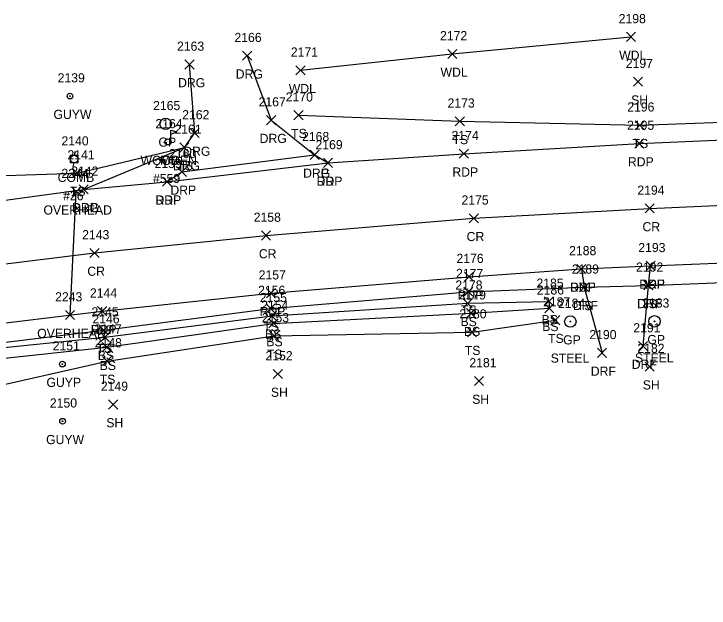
# Model space of a CAD drawing. Extents: x 1611797 to 1633212, y 298978 to 305475.
# Drawn here: x 1614651.7 to 1614804, y 301422 to 301552.1 of the extents above; entities that cross this region are included whole.
import ezdxf

# ---------------------------------------------------------------- set-up
doc = ezdxf.new("R2010")
doc.units = 0
for name, color, linetype in [('L_A', 7, 'Continuous'), ('L_C', 7, 'Continuous'), ('L_I', 7, 'Continuous'), ('L_TIC', 7, 'Continuous'), ('LAWA', 7, 'Continuous'), ('LELB', 7, 'Continuous'), ('LMB', 7, 'Continuous'), ('P_A', 7, 'Continuous'), ('P_I', 7, 'Continuous'), ('P_TIC', 7, 'Continuous'), ('PET', 7, 'Continuous'), ('PRC', 7, 'Continuous'), ('R_A', 7, 'Continuous'), ('R_C', 7, 'Continuous'), ('R_I', 7, 'Continuous'), ('R_TIC', 7, 'Continuous'), ('RDF', 7, 'Continuous'), ('RDG', 7, 'Continuous'), ('RDP', 7, 'Continuous'), ('RGP', 7, 'Continuous'), ('U_A', 7, 'Continuous'), ('U_C', 7, 'Continuous'), ('U_I', 7, 'Continuous'), ('U_TIC', 7, 'Continuous'), ('UCO', 7, 'Continuous'), ('UP', 7, 'Continuous'), ('UPGW', 7, 'Continuous')]:
    doc.layers.add(name, color=color, linetype=linetype)

msp = doc.modelspace()

# ---------------------------------------------------------------- linework, layer by layer
at = {"layer": 'L_TIC'}
for points in [[(1614785.88, 301546.07), (1614787.88, 301548.07)], [(1614787.88, 301546.07), (1614785.88, 301548.07)], [(1614746.75, 301542.34), (1614748.75, 301544.34)], [(1614748.75, 301542.34), (1614746.75, 301544.34)], [(1614713.52, 301538.76), (1614715.52, 301540.76)], [(1614715.52, 301538.76), (1614713.52, 301540.76)], [(1614787.44, 301536.26), (1614789.44, 301538.26)], [(1614789.44, 301536.26), (1614787.44, 301538.26)], [(1614713.06, 301528.93), (1614715.06, 301530.93)], [(1614715.06, 301528.93), (1614713.06, 301530.93)], [(1614748.4, 301527.59), (1614750.4, 301529.59)], [(1614750.4, 301527.59), (1614748.4, 301529.59)], [(1614787.82, 301526.73), (1614789.82, 301528.73)], [(1614789.82, 301526.73), (1614787.82, 301528.73)], [(1614688.07, 301521.87), (1614690.07, 301523.87)], [(1614690.07, 301521.87), (1614688.07, 301523.87)], [(1614664.6, 301516.26), (1614666.6, 301518.26)], [(1614666.6, 301516.26), (1614664.6, 301518.26)], [(1614775.62, 301491.25), (1614777.62, 301493.25)], [(1614777.62, 301491.25), (1614775.62, 301493.25)], [(1614789.7, 301491.68), (1614791.7, 301493.68)], [(1614791.7, 301491.68), (1614789.7, 301493.68)], [(1614750.26, 301490.29), (1614752.26, 301492.29)], [(1614752.26, 301490.29), (1614750.26, 301492.29)], [(1614767.89, 301488.17), (1614769.89, 301490.17)], [(1614769.89, 301488.17), (1614767.89, 301490.17)], [(1614706.96, 301486.6), (1614708.96, 301488.6)], [(1614708.96, 301486.6), (1614706.96, 301488.6)], [(1614750.11, 301487.75), (1614752.11, 301489.75)], [(1614752.11, 301487.75), (1614750.11, 301489.75)], [(1614768.01, 301486.67), (1614770.01, 301488.67)], [(1614770.01, 301486.67), (1614768.01, 301488.67)], [(1614768.01, 301486.67), (1614770.01, 301488.67)], [(1614770.01, 301486.67), (1614768.01, 301488.67)], [(1614707.28, 301485.02), (1614709.28, 301487.02)], [(1614709.28, 301485.02), (1614707.28, 301487.02)], [(1614750.86, 301485.59), (1614752.86, 301487.59)], [(1614752.86, 301485.59), (1614750.86, 301487.59)], [(1614707.59, 301483.35), (1614709.59, 301485.35)], [(1614709.59, 301483.35), (1614707.59, 301485.35)], [(1614769.32, 301484.06), (1614771.32, 301486.06)], [(1614771.32, 301484.06), (1614769.32, 301486.06)], [(1614670.43, 301481.88), (1614672.43, 301483.88)], [(1614672.43, 301481.88), (1614670.43, 301483.88)], [(1614670.68, 301480.35), (1614672.68, 301482.35)], [(1614672.68, 301480.35), (1614670.68, 301482.35)], [(1614707.74, 301480.62), (1614709.74, 301482.62)], [(1614709.74, 301480.62), (1614707.74, 301482.62)], [(1614751.08, 301481.44), (1614753.08, 301483.44)], [(1614753.08, 301481.44), (1614751.08, 301483.44)], [(1614671.08, 301478.14), (1614673.08, 301480.14)], [(1614673.08, 301478.14), (1614671.08, 301480.14)], [(1614671.14, 301475.12), (1614673.14, 301477.12)], [(1614673.14, 301475.12), (1614671.14, 301477.12)], [(1614789.98, 301473.89), (1614791.98, 301475.89)], [(1614791.98, 301473.89), (1614789.98, 301475.89)], [(1614708.54, 301472.28), (1614710.54, 301474.28)], [(1614710.54, 301472.28), (1614708.54, 301474.28)], [(1614752.62, 301470.74), (1614754.62, 301472.74)], [(1614754.62, 301470.74), (1614752.62, 301472.74)], [(1614672.49, 301465.61), (1614674.49, 301467.61)], [(1614674.49, 301465.61), (1614672.49, 301467.61)]]:
    msp.add_lwpolyline(points, dxfattribs=at)
at = {"layer": 'LAWA'}
msp.add_lwpolyline([(1614714.52, 301539.76), (1614747.75, 301543.34), (1614786.88, 301547.07)], dxfattribs=at)
at = {"layer": 'LELB'}
for points in [[(1614714.06, 301529.93), (1614749.4, 301528.59), (1614788.82, 301527.73), (1614827.02, 301529.13), (1614870.26, 301533.86), (1614915.48, 301532.19), (1614947.38, 301533.98), (1615003.28, 301531.36), (1615030.43, 301531.47), (1615038.75, 301539.3), (1615042.32, 301548.18)], [(1614431.54, 301482.84), (1614462.05, 301487.3), (1614494.87, 301495.91), (1614519.67, 301504.14), (1614559.97, 301510.18), (1614596.29, 301511.9), (1614638.57, 301516.35), (1614665.6, 301517.26), (1614689.07, 301522.87)], [(1614397.99, 301442.92), (1614427.41, 301447.99), (1614467.33, 301454.21), (1614500.14, 301459.48), (1614527.47, 301463.02), (1614565.7, 301469.85), (1614602.21, 301474.32), (1614642.74, 301479.39), (1614671.43, 301482.88), (1614707.96, 301487.6), (1614751.26, 301491.29), (1614776.62, 301492.25), (1614790.7, 301492.68), (1614828.78, 301494.15), (1614870.95, 301494.61), (1614916.31, 301494.84), (1614940.92, 301495.39), (1614991.32, 301496.48), (1615024.25, 301496.97), (1615079.65, 301497.8)], [(1614388.68, 301423.66), (1614397.1, 301437.78), (1614427.86, 301446.85), (1614467.6, 301452.72), (1614486.89, 301454.32), (1614500.85, 301457.06), (1614528.06, 301461.07), (1614566.51, 301467.1), (1614602.68, 301472.69), (1614643.17, 301478.4), (1614671.68, 301481.35), (1614708.28, 301486.02), (1614751.11, 301488.75), (1614768.89, 301489.17), (1614769.01, 301487.67)], [(1614397.1, 301437.78), (1614428.41, 301444.54), (1614468.12, 301450.7), (1614487.22, 301452.99), (1614500.88, 301455.16), (1614528.71, 301458.71), (1614567.07, 301464.5), (1614603.04, 301470.65), (1614643.55, 301476.12), (1614672.08, 301479.14), (1614708.59, 301484.35), (1614751.86, 301486.59), (1614769.01, 301487.67)], [(1614398.42, 301422.03), (1614407.58, 301431.9), (1614428.91, 301436.83), (1614470.35, 301441.15), (1614511.39, 301446.9), (1614531.19, 301448.83), (1614567.14, 301456.99), (1614604.55, 301462.93), (1614643.66, 301469.63), (1614672.14, 301476.12), (1614708.74, 301481.62), (1614752.08, 301482.44), (1614770.32, 301485.06)]]:
    msp.add_lwpolyline(points, dxfattribs=at)
at = {"layer": 'LMB'}
for p, q in [((1614686.12, 301526.68), (1614687.41, 301526.3)), ((1614686.12, 301524.09), (1614686.12, 301526.68)), ((1614686.12, 301525.78), (1614687.4, 301526.29)), ((1614685.47, 301524.08), (1614685.47, 301524.08))]:
    msp.add_line(p, q, dxfattribs=at)
msp.add_circle((1614685.47, 301524.08), 0.656, dxfattribs=at)
at = {"layer": 'P_TIC'}
for points in [[(1614787.72, 301522.73), (1614789.72, 301524.73)], [(1614789.72, 301522.73), (1614787.72, 301524.73)], [(1614749.28, 301520.49), (1614751.28, 301522.49)], [(1614751.28, 301520.49), (1614749.28, 301522.49)], [(1614719.54, 301518.49), (1614721.54, 301520.49)], [(1614721.54, 301518.49), (1614719.54, 301520.49)], [(1614684.25, 301514.36), (1614686.25, 301516.36)], [(1614686.25, 301514.36), (1614684.25, 301516.36)], [(1614666, 301512.69), (1614668, 301514.69)], [(1614668, 301512.69), (1614666, 301514.69)], [(1614789.97, 301508.52), (1614791.97, 301510.52)], [(1614791.97, 301508.52), (1614789.97, 301510.52)], [(1614751.46, 301506.37), (1614753.46, 301508.37)], [(1614753.46, 301506.37), (1614751.46, 301508.37)], [(1614705.96, 301502.6), (1614707.96, 301504.6)], [(1614707.96, 301502.6), (1614705.96, 301504.6)], [(1614668.39, 301498.77), (1614670.39, 301500.77)], [(1614670.39, 301498.77), (1614668.39, 301500.77)], [(1614790.19, 301495.95), (1614792.19, 301497.95)], [(1614792.19, 301495.95), (1614790.19, 301497.95)], [(1614775.03, 301495.28), (1614777.03, 301497.28)], [(1614777.03, 301495.28), (1614775.03, 301497.28)], [(1614750.42, 301493.58), (1614752.42, 301495.58)], [(1614752.42, 301493.58), (1614750.42, 301495.58)], [(1614707.04, 301489.97), (1614709.04, 301491.97)], [(1614709.04, 301489.97), (1614707.04, 301491.97)], [(1614670.08, 301486.02), (1614672.08, 301488.02)], [(1614672.08, 301486.02), (1614670.08, 301488.02)]]:
    msp.add_lwpolyline(points, dxfattribs=at)
at = {"layer": 'PET'}
for points in [[(1614353.18, 301466.45), (1614396.11, 301473.72), (1614432.71, 301479.37), (1614462.6, 301484.02), (1614495.94, 301489.18), (1614521.44, 301493.19), (1614561.65, 301499.05), (1614597.5, 301504.18), (1614639.09, 301509.88), (1614667, 301513.69), (1614685.25, 301515.36), (1614720.54, 301519.49), (1614750.28, 301521.49), (1614788.72, 301523.73), (1614827.23, 301525.41)], [(1614357.07, 301439.35), (1614396.41, 301445), (1614427.12, 301450.7), (1614466.81, 301457.75), (1614499.64, 301462.71), (1614526.79, 301467.08), (1614565.37, 301472.77), (1614601.94, 301478.15), (1614641.98, 301483.54), (1614671.08, 301487.02), (1614708.04, 301490.97), (1614751.42, 301494.58), (1614776.03, 301496.28), (1614791.19, 301496.95), (1614828.91, 301498.47)]]:
    msp.add_lwpolyline(points, dxfattribs=at)
at = {"layer": 'PRC'}
msp.add_lwpolyline([(1614363.42, 301453.92), (1614394.65, 301458.77), (1614425.51, 301463.7), (1614464.79, 301470.26), (1614497.93, 301475.41), (1614523.39, 301479.49), (1614563.69, 301485.47), (1614599.72, 301490.73), (1614640.43, 301496.25), (1614669.39, 301499.77), (1614706.96, 301503.6), (1614752.46, 301507.37), (1614790.97, 301509.52), (1614828.29, 301511.16), (1614871, 301512.22), (1614916.11, 301513.02), (1614945.75, 301513.16), (1615002.39, 301512.78), (1615048.11, 301512.72), (1615086.61, 301512.12), (1615113.26, 301511.44), (1615142.89, 301510.74), (1615196.64, 301509.68)], dxfattribs=at)
at = {"layer": 'R_TIC'}
for points in [[(1614701.83, 301541.95), (1614703.83, 301543.95)], [(1614703.83, 301541.95), (1614701.83, 301543.95)], [(1614689.2, 301540.04), (1614691.2, 301542.04)], [(1614691.2, 301540.04), (1614689.2, 301542.04)], [(1614707.07, 301527.85), (1614709.07, 301529.85)], [(1614709.07, 301527.85), (1614707.07, 301529.85)], [(1614690.34, 301525.04), (1614692.34, 301527.04)], [(1614692.34, 301525.04), (1614690.34, 301527.04)], [(1614688.07, 301521.87), (1614690.07, 301523.87)], [(1614690.07, 301521.87), (1614688.07, 301523.87)], [(1614716.59, 301520.25), (1614718.59, 301522.25)], [(1614718.59, 301520.25), (1614716.59, 301522.25)], [(1614716.59, 301520.25), (1614718.59, 301522.25)], [(1614718.59, 301520.25), (1614716.59, 301522.25)], [(1614719.54, 301518.49), (1614721.54, 301520.49)], [(1614721.54, 301518.49), (1614719.54, 301520.49)], [(1614687.53, 301516.53), (1614689.53, 301518.53)], [(1614689.53, 301516.53), (1614687.53, 301518.53)], [(1614684.25, 301514.36), (1614686.25, 301516.36)], [(1614686.25, 301514.36), (1614684.25, 301516.36)], [(1614666, 301512.69), (1614668, 301514.69)], [(1614668, 301512.69), (1614666, 301514.69)], [(1614790.19, 301495.95), (1614792.19, 301497.95)], [(1614792.19, 301495.95), (1614790.19, 301497.95)], [(1614775.03, 301495.28), (1614777.03, 301497.28)], [(1614777.03, 301495.28), (1614775.03, 301497.28)], [(1614775.62, 301491.25), (1614777.62, 301493.25)], [(1614777.62, 301491.25), (1614775.62, 301493.25)], [(1614789.7, 301491.68), (1614791.7, 301493.68)], [(1614791.7, 301491.68), (1614789.7, 301493.68)], [(1614788.52, 301478.39), (1614790.52, 301480.39)], [(1614790.52, 301478.39), (1614788.52, 301480.39)], [(1614779.55, 301476.9), (1614781.55, 301478.9)], [(1614781.55, 301476.9), (1614779.55, 301478.9)]]:
    msp.add_lwpolyline(points, dxfattribs=at)
at = {"layer": 'RDF'}
for points in [[(1614776.03, 301496.28), (1614776.62, 301492.25), (1614780.55, 301477.9)], [(1614789.52, 301479.39), (1614790.7, 301492.68), (1614791.19, 301496.95)]]:
    msp.add_lwpolyline(points, dxfattribs=at)
at = {"layer": 'RDG'}
for points in [[(1614702.83, 301542.95), (1614708.07, 301528.85), (1614717.59, 301521.25)], [(1614667, 301513.69), (1614689.07, 301522.87), (1614691.34, 301526.04), (1614690.2, 301541.04)]]:
    msp.add_lwpolyline(points, dxfattribs=at)
at = {"layer": 'RDP'}
msp.add_lwpolyline([(1614685.25, 301515.36), (1614688.53, 301517.53), (1614717.59, 301521.25), (1614720.54, 301519.49)], dxfattribs=at)
at = {"layer": 'RGP'}
for p, q in [((1614684.97, 301528.04), (1614684.97, 301528.04)), ((1614773.6, 301484.75), (1614773.6, 301484.75)), ((1614792.03, 301484.81), (1614792.03, 301484.81))]:
    msp.add_line(p, q, dxfattribs=at)
for centre, radius in [((1614684.97, 301528.04), 1.25), ((1614684.97, 301528.04), 0.0833), ((1614773.6, 301484.75), 1.25), ((1614792.03, 301484.81), 1.25), ((1614773.6, 301484.75), 0.0833), ((1614792.03, 301484.81), 0.0833)]:
    msp.add_circle(centre, radius, dxfattribs=at)
at = {"layer": 'U_TIC'}
for points in [[(1614664.4, 301512.18), (1614666.4, 301514.18)], [(1614666.4, 301512.18), (1614664.4, 301514.18)], [(1614663.03, 301485.17), (1614665.03, 301487.17)], [(1614665.03, 301485.17), (1614663.03, 301487.17)]]:
    msp.add_lwpolyline(points, dxfattribs=at)
at = {"layer": 'UCO'}
msp.add_lwpolyline([(1614664.03, 301486.17), (1614665.4, 301513.18)], dxfattribs=at)
at = {"layer": 'UP'}
for p, q in [((1614665.19, 301521.98), (1614664.94, 301521.15)), ((1614664.1, 301519.48), (1614664.1, 301521.15)), ((1614664.1, 301521.15), (1614665.77, 301521.15)), ((1614665.77, 301521.15), (1614665.77, 301519.48)), ((1614665.77, 301519.48), (1614664.1, 301519.48)), ((1614664.69, 301518.65), (1614664.94, 301519.48)), ((1614664.94, 301520.31), (1614664.94, 301520.31))]:
    msp.add_line(p, q, dxfattribs=at)
msp.add_circle((1614664.94, 301520.31), 0.833, dxfattribs=at)
at = {"layer": 'UPGW'}
for centre, radius in [((1614664.02, 301534.11), 0.625), ((1614664.02, 301534.11), 0.0833), ((1614662.36, 301475.44), 0.625), ((1614662.36, 301475.44), 0.0833), ((1614662.4, 301462.93), 0.625), ((1614662.4, 301462.93), 0.0833)]:
    msp.add_circle(centre, radius, dxfattribs=at)

# ---------------------------------------------------------------- texts
at = {"layer": 'L_A'}
for s, p in [('WDL', (1614784.3, 301542.07)), ('WDL', (1614745.17, 301538.34)), ('WDL', (1614711.94, 301534.76)), ('SH', (1614786.93, 301532.26)), ('TS', (1614712.47, 301524.93)), ('TS', (1614747.81, 301523.59)), ('TS', (1614787.23, 301522.73)), ('MB', (1614683.77, 301519.08)), ('TS', (1614687.48, 301517.87)), ('TS', (1614664.01, 301512.26)), ('TS', (1614775.03, 301487.25)), ('TS', (1614789.11, 301487.68)), ('TS', (1614749.67, 301486.29)), ('BS', (1614749.55, 301483.75)), ('BS', (1614767.33, 301484.17)), ('TS', (1614706.37, 301482.6)), ('BS', (1614767.45, 301482.67)), ('BS', (1614767.45, 301482.67)), ('BS', (1614706.72, 301481.02)), ('BS', (1614750.3, 301481.59)), ('BS', (1614707.03, 301479.35)), ('TS', (1614768.73, 301480.06)), ('TS', (1614669.84, 301477.88)), ('TS', (1614750.49, 301477.44)), ('BS', (1614670.12, 301476.35)), ('TS', (1614707.15, 301476.62)), ('BS', (1614670.52, 301474.14)), ('TS', (1614670.54, 301471.12)), ('SH', (1614789.47, 301469.89)), ('SH', (1614708.03, 301468.28)), ('SH', (1614752.11, 301466.74)), ('SH', (1614671.98, 301461.61))]:
    msp.add_text(s, height=2, dxfattribs=at).set_placement(p)
at = {"layer": 'L_C'}
msp.add_text('#559', height=2, dxfattribs=at).set_placement((1614682.2, 301515.08))
at = {"layer": 'L_I'}
for s, p in [('2198', (1614784.19, 301550.07)), ('2172', (1614745.06, 301546.34)), ('2171', (1614712.39, 301542.76)), ('2197', (1614785.75, 301540.26)), ('2170', (1614711.28, 301532.93)), ('2173', (1614746.71, 301531.59)), ('2196', (1614786.07, 301530.73)), ('2164', (1614682.73, 301527.08)), ('2161', (1614686.9, 301525.87)), ('2141', (1614663.48, 301520.26)), ('2192', (1614788, 301495.68)), ('2177', (1614748.57, 301494.29)), ('2189', (1614773.92, 301495.25)), ('2178', (1614748.42, 301491.75)), ('2185', (1614766.19, 301492.17)), ('2156', (1614705.22, 301490.6)), ('2179', (1614749.16, 301489.59)), ('2186', (1614766.26, 301490.67)), ('2186', (1614766.26, 301490.67)), ('2155', (1614705.59, 301489.02)), ('2187', (1614767.63, 301488.06)), ('2154', (1614705.9, 301487.35)), ('2145', (1614668.73, 301485.88)), ('2180', (1614749.3, 301485.44)), ('2146', (1614668.94, 301484.35)), ('2153', (1614706.05, 301484.62)), ('2147', (1614669.39, 301482.14)), ('2148', (1614669.44, 301479.12)), ('2182', (1614788.29, 301477.89)), ('2152', (1614706.84, 301476.28)), ('2181', (1614751.49, 301474.74)), ('2149', (1614670.79, 301469.61))]:
    msp.add_text(s, height=2, dxfattribs=at).set_placement(p)
at = {"layer": 'P_A'}
for s, p in [('RDP', (1614786.21, 301518.73)), ('RDP', (1614747.77, 301516.49)), ('RDP', (1614718.03, 301514.49)), ('RDP', (1614682.74, 301510.36)), ('RDP', (1614664.49, 301508.69)), ('CR', (1614789.41, 301504.52)), ('CR', (1614750.89, 301502.37)), ('CR', (1614705.39, 301498.6)), ('CR', (1614667.82, 301494.77)), ('RDP', (1614773.52, 301491.28)), ('RDP', (1614788.68, 301491.95)), ('RDP', (1614748.9, 301489.58)), ('RDP', (1614705.53, 301485.97)), ('RDP', (1614668.57, 301482.02))]:
    msp.add_text(s, height=2, dxfattribs=at).set_placement(p)
at = {"layer": 'P_I'}
for s, p in [('2195', (1614786.03, 301526.73)), ('2174', (1614747.59, 301524.49)), ('2169', (1614717.79, 301522.49)), ('2159', (1614682.55, 301518.36)), ('2142', (1614664.3, 301516.69)), ('2194', (1614788.28, 301512.52)), ('2175', (1614749.77, 301510.37)), ('2158', (1614704.26, 301506.6)), ('2143', (1614666.69, 301502.77)), ('2188', (1614773.34, 301499.28)), ('2193', (1614788.49, 301499.95)), ('2176', (1614748.67, 301497.58)), ('2157', (1614705.35, 301493.97)), ('2144', (1614668.39, 301490.02))]:
    msp.add_text(s, height=2, dxfattribs=at).set_placement(p)
at = {"layer": 'R_A'}
for s, p in [('DRG', (1614700.32, 301537.95)), ('DRG', (1614687.69, 301536.04)), ('GP', (1614683.4, 301523.04)), ('DRG', (1614705.56, 301523.85)), ('DRG', (1614688.83, 301521.04)), ('DRG', (1614686.56, 301517.87)), ('DRG', (1614715.08, 301516.25)), ('DRP', (1614715.08, 301516.25)), ('DRP', (1614718.03, 301514.49)), ('DRP', (1614686.01, 301512.53)), ('DRP', (1614682.74, 301510.36)), ('DRG', (1614664.49, 301508.69)), ('DRF', (1614773.57, 301491.28)), ('DRF', (1614788.72, 301491.95)), ('DRF', (1614774.16, 301487.25)), ('DRF', (1614788.23, 301487.68)), ('GP', (1614772.03, 301479.75)), ('GP', (1614790.47, 301479.81)), ('DRF', (1614787.05, 301474.39)), ('DRF', (1614778.08, 301472.9))]:
    msp.add_text(s, height=2, dxfattribs=at).set_placement(p)
at = {"layer": 'R_C'}
for s, p in [('WOODEN', (1614679.48, 301519.04)), ('STEEL', (1614769.31, 301475.75)), ('STEEL', (1614787.75, 301475.81))]:
    msp.add_text(s, height=2, dxfattribs=at).set_placement(p)
at = {"layer": 'R_I'}
for s, p in [('2166', (1614700.04, 301545.95)), ('2163', (1614687.46, 301544.04)), ('2165', (1614682.23, 301531.04)), ('2167', (1614705.33, 301531.85)), ('2162', (1614688.6, 301529.04)), ('2161', (1614686.9, 301525.87)), ('2168', (1614714.85, 301524.25)), ('2168', (1614714.85, 301524.25)), ('2169', (1614717.79, 301522.49)), ('2160', (1614685.7, 301520.53)), ('2159', (1614682.55, 301518.36)), ('2142', (1614664.3, 301516.69)), ('2188', (1614773.34, 301499.28)), ('2193', (1614788.49, 301499.95)), ('2192', (1614788, 301495.68)), ('2189', (1614773.92, 301495.25)), ('2184', (1614770.9, 301487.75)), ('2183', (1614789.34, 301487.81)), ('2191', (1614787.39, 301482.39)), ('2190', (1614777.77, 301480.9))]:
    msp.add_text(s, height=2, dxfattribs=at).set_placement(p)
at = {"layer": 'U_A'}
for s, p in [('GUYW', (1614660.41, 301529.11)), ('COMB', (1614661.32, 301515.31)), ('OVERHEAD', (1614658.21, 301508.18)), ('OVERHEAD', (1614656.84, 301481.17)), ('GUYP', (1614658.87, 301470.44)), ('GUYW', (1614658.79, 301457.93))]:
    msp.add_text(s, height=2, dxfattribs=at).set_placement(p)
at = {"layer": 'U_C'}
msp.add_text('#26', height=2, dxfattribs=at).set_placement((1614662.52, 301511.31))
at = {"layer": 'U_I'}
for s, p in [('2139', (1614661.32, 301537.11)), ('2140', (1614662.16, 301523.31)), ('2244', (1614662.14, 301516.18)), ('2243', (1614660.77, 301489.17)), ('2151', (1614660.23, 301478.44)), ('2150', (1614659.62, 301465.93))]:
    msp.add_text(s, height=2, dxfattribs=at).set_placement(p)

doc.saveas('drawing.dxf')
